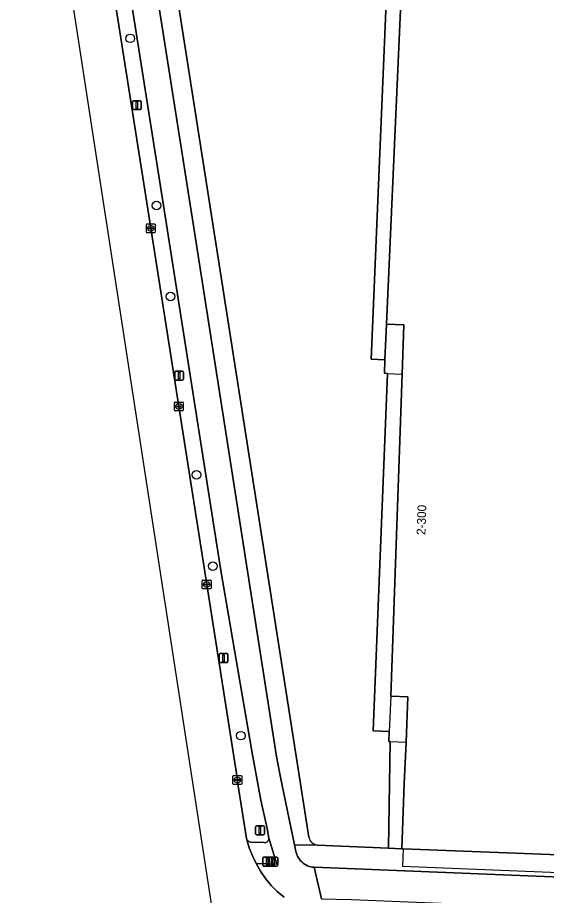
# Model space of a CAD drawing. Extents: x 160888 to 161385, y 386490 to 386908.
# Drawn here: x 160887.8 to 160947.8, y 386737.3 to 386837.1 of the extents above; entities that cross this region are included whole.
import ezdxf

# ---------------------------------------------------------------- set-up
doc = ezdxf.new("R2010")
doc.units = 0
for name, color, linetype in [('IMGEO_Berm_groen', 7, 'Continuous'), ('IMGEO_Boom', 7, 'Continuous'), ('IMGEO_Drukknoppaal', 7, 'Continuous'), ('IMGEO_Erf', 7, 'Continuous'), ('IMGEO_Fietspad_gesloten', 7, 'Continuous'), ('IMGEO_Groenvoorziening', 7, 'Continuous'), ('IMGEO_Kolk', 7, 'Continuous'), ('IMGEO_Lichtmast', 7, 'Continuous'), ('IMGEO_Pand', 7, 'Continuous'), ('IMGEO_Pand_nummerreeks', 7, 'Continuous'), ('IMGEO_Pand_overbouw', 7, 'Continuous'), ('IMGEO_Rijbaan_lokaal_gesloten', 7, 'Continuous'), ('IMGEO_Verkeersbordpaal', 7, 'Continuous'), ('IMGEO_Verkeersregelinstallatiepaal', 7, 'Continuous'), ('IMGEO_Voetpad_gesloten', 7, 'Continuous'), ('IMGEO_Voetpad_open', 7, 'Continuous')]:
    doc.layers.add(name, color=color, linetype=linetype)

msp = doc.modelspace()

# ---------------------------------------------------------------- linework, layer by layer
at = {"layer": 'IMGEO_Berm_groen'}
for points in [[(160895.489, 386860.369), (160895.508, 386860.258), (160895.636, 386859.48), (160895.937, 386857.577), (160898.944, 386838.332), (160902.899, 386813.113), (160906.087, 386792.878), (160909.252, 386772.655), (160912.737, 386750.44), (160912.804, 386750), (160913.758, 386743.775)], [(160904.689, 386813.559), (160897.429, 386859.589), (160897.273, 386860.565)], [(160916.31, 386743.822), (160916.107, 386744.917), (160915.406, 386748.161), (160915.067, 386750), (160914.38, 386753.725), (160910.872, 386774.235), (160904.689, 386813.559)], [(160914.246, 386743.387), (160915.791, 386743.32)]]:
    msp.add_lwpolyline(points, dxfattribs=at)
for centre, radius, start, end in [((160914.327, 386743.989), 0.608, 200.64836, 262.37649), ((160915.811, 386743.819), 0.499, 267.70354, 0.38865)]:
    msp.add_arc(centre, radius, start, end, dxfattribs=at)
at = {"layer": 'IMGEO_Boom'}
for centre in [(160900.576, 386834.696), (160903.554, 386815.703), (160905.132, 386805.364), (160908.087, 386785.118), (160909.949, 386774.72), (160913.128, 386755.473)]:
    msp.add_circle(centre, 0.489, dxfattribs=at)
at = {"layer": 'IMGEO_Drukknoppaal'}
for p, q in [((160916.348, 386740.753), (160916.348, 386741.553)), ((160916.348, 386741.553), (160916.348, 386740.753)), ((160916.448, 386741.653), (160917.238, 386741.653)), ((160917.238, 386741.653), (160916.448, 386741.653)), ((160917.338, 386741.553), (160917.338, 386740.753)), ((160917.338, 386740.753), (160917.338, 386741.553)), ((160917.238, 386740.653), (160916.448, 386740.653)), ((160916.448, 386740.653), (160917.238, 386740.653))]:
    msp.add_line(p, q, dxfattribs=at)
msp.add_lwpolyline([(160916.768, 386741.528), (160916.918, 386741.528), (160916.918, 386740.778), (160916.768, 386740.778), (160916.768, 386741.528)], dxfattribs=at)
for centre, start, end in [((160916.448, 386741.553), 90, 180), ((160916.448, 386741.553), 90, 180), ((160917.238, 386741.553), 0, 90), ((160917.238, 386741.553), 360, 90), ((160916.448, 386740.753), 180, 270), ((160916.448, 386740.753), 180, 270), ((160917.238, 386740.753), 270, 0), ((160917.238, 386740.753), 270, 0)]:
    msp.add_arc(centre, 0.1, start, end, dxfattribs=at)
at = {"layer": 'IMGEO_Erf'}
msp.add_lwpolyline([(160931.458, 386796.556), (160931.656, 386802.139), (160929.668, 386802.21), (160929.5, 386798.18), (160929.436, 386796.639), (160929.806, 386796.624), (160928.176, 386756.029), (160929.987, 386755.938), (160929.938, 386754.813), (160930.114, 386754.806), (160930.028, 386750), (160929.897, 386742.707), (160931.403, 386742.634), (160931.703, 386750), (160931.896, 386754.732), (160932.106, 386759.876), (160930.162, 386759.955)], close=True, dxfattribs=at)
at = {"layer": 'IMGEO_Fietspad_gesloten'}
for points in [[(160922.279, 386736.94), (160921.46, 386740.524), (160921.286, 386740.54), (160921.091, 386740.575), (160920.9, 386740.627), (160920.714, 386740.696), (160920.534, 386740.781), (160920.364, 386740.882), (160920.203, 386740.998), (160920.052, 386741.128), (160919.915, 386741.27), (160919.79, 386741.425), (160919.68, 386741.59), (160919.584, 386741.764), (160919.505, 386741.946), (160919.443, 386742.134), (160919.397, 386742.327), (160919.245, 386743.063), (160917.807, 386750), (160917.572, 386751.136), (160917.197, 386753.124), (160907.589, 386814.399), (160899.722, 386864.375)], [(160897.429, 386859.589), (160904.689, 386813.559), (160910.872, 386774.235), (160914.38, 386753.725), (160915.067, 386750), (160915.406, 386748.161), (160916.107, 386744.917), (160916.31, 386743.822), (160917.205, 386740.862), (160914.891, 386740.934), (160915.378, 386740.062), (160915.94, 386739.237), (160916.574, 386738.465), (160917.275, 386737.753), (160918.036, 386737.106)], [(160992.282, 386737.671), (160955.08, 386739.168), (160921.46, 386740.524), (160922.279, 386736.94), (160925.661, 386736.849), (160955.395, 386735.634), (160990.998, 386734.2), (160994.79, 386734.023), (160998.243, 386734.057), (161000, 386734.178), (161002.436, 386734.648), (161005.984, 386735.898), (161019.969, 386741.623)]]:
    msp.add_lwpolyline(points, dxfattribs=at)
at = {"layer": 'IMGEO_Groenvoorziening'}
for points in [[(160930.929, 386869.413), (160919.86, 386869.902), (160901.002, 386870.642), (160909.808, 386814.589), (160919.923, 386750), (160920.871, 386743.948)], [(160921.858, 386743.044), (160929.897, 386742.707), (160930.028, 386750), (160930.114, 386754.806), (160929.938, 386754.813), (160929.987, 386755.938), (160928.176, 386756.029), (160929.806, 386796.624), (160929.436, 386796.639), (160929.5, 386798.18), (160927.927, 386798.235), (160930.929, 386869.413)]]:
    msp.add_lwpolyline(points, dxfattribs=at)
msp.add_arc((160921.926, 386744.109), 1.067, 188.65599, 266.37045, dxfattribs=at)
at = {"layer": 'IMGEO_Kolk'}
for p, q in [((160902.398, 386812.687), (160902.398, 386813.539)), ((160902.473, 386813.613), (160903.325, 386813.613)), ((160902.657, 386813.107), (160902.657, 386813.119)), ((160903.095, 386813.07), (160902.697, 386813.07)), ((160902.7, 386813.156), (160903.098, 386813.156)), ((160902.909, 386812.833), (160902.884, 386812.833)), ((160902.886, 386813.393), (160902.911, 386813.393)), ((160903.141, 386813.119), (160903.141, 386813.107)), ((160903.399, 386813.539), (160903.399, 386812.687)), ((160903.325, 386812.613), (160902.473, 386812.613)), ((160905.586, 386792.452), (160905.586, 386793.304)), ((160905.661, 386793.378), (160906.513, 386793.378)), ((160905.845, 386792.872), (160905.845, 386792.884)), ((160906.283, 386792.835), (160905.885, 386792.835)), ((160905.888, 386792.921), (160906.286, 386792.921)), ((160906.074, 386793.158), (160906.099, 386793.158)), ((160906.329, 386792.884), (160906.329, 386792.872)), ((160906.587, 386793.304), (160906.587, 386792.452)), ((160906.513, 386792.378), (160905.661, 386792.378)), ((160906.097, 386792.598), (160906.072, 386792.598)), ((160908.751, 386772.229), (160908.751, 386773.081)), ((160908.826, 386773.155), (160909.678, 386773.155)), ((160909.239, 386772.935), (160909.264, 386772.935)), ((160909.752, 386773.081), (160909.752, 386772.229)), ((160909.678, 386772.155), (160908.826, 386772.155)), ((160909.01, 386772.649), (160909.01, 386772.661)), ((160909.448, 386772.612), (160909.05, 386772.612)), ((160909.053, 386772.698), (160909.451, 386772.698)), ((160909.262, 386772.375), (160909.237, 386772.375)), ((160909.494, 386772.661), (160909.494, 386772.649)), ((160912.311, 386750.94), (160913.163, 386750.94)), ((160912.236, 386750.014), (160912.236, 386750.866)), ((160913.163, 386749.94), (160912.311, 386749.94)), ((160912.495, 386750.434), (160912.495, 386750.446)), ((160912.933, 386750.397), (160912.535, 386750.397)), ((160912.538, 386750.483), (160912.936, 386750.483)), ((160912.747, 386750.16), (160912.722, 386750.16)), ((160912.724, 386750.72), (160912.749, 386750.72)), ((160912.979, 386750.446), (160912.979, 386750.434)), ((160913.237, 386750.866), (160913.237, 386750.014))]:
    msp.add_line(p, q, dxfattribs=at)
for points in [[(160902.398, 386812.687), (160902.398, 386813.539)], [(160902.473, 386813.613), (160903.325, 386813.613)], [(160903.399, 386813.539), (160903.399, 386812.687)], [(160903.325, 386812.613), (160902.473, 386812.613)], [(160905.586, 386792.452), (160905.586, 386793.304)], [(160905.661, 386793.378), (160906.513, 386793.378)], [(160906.587, 386793.304), (160906.587, 386792.452)], [(160906.513, 386792.378), (160905.661, 386792.378)], [(160908.751, 386772.229), (160908.751, 386773.081)], [(160908.826, 386773.155), (160909.678, 386773.155)], [(160909.752, 386773.081), (160909.752, 386772.229)], [(160909.678, 386772.155), (160908.826, 386772.155)], [(160912.311, 386750.94), (160913.163, 386750.94)], [(160912.236, 386750.014), (160912.236, 386750.866)], [(160913.163, 386749.94), (160912.311, 386749.94)], [(160913.237, 386750.866), (160913.237, 386750.014)]]:
    msp.add_lwpolyline(points, dxfattribs=at)
for centre, radius, start, end in [((160902.475, 386813.537), 0.0765, 91.55205, 178.44795), ((160902.475, 386813.537), 0.0765, 91.55205, 178.44795), ((160902.697, 386813.116), 0.0403, 85.87752, 175.75265), ((160902.694, 386813.106), 0.0366, 178.93798, 274.71019), ((160903.098, 386813.113), 0.043, 264.86636, 352.45326), ((160903.102, 386813.118), 0.0386, 1.73085, 96.63898), ((160903.323, 386813.537), 0.0765, 1.55205, 88.44795), ((160903.323, 386813.537), 0.0765, 1.55205, 88.44795), ((160902.475, 386812.689), 0.0765, 181.55205, 268.44795), ((160902.475, 386812.689), 0.0765, 181.55205, 268.44795), ((160903.323, 386812.689), 0.0765, 271.55205, 358.44795), ((160903.323, 386812.689), 0.0765, 271.55205, 358.44795), ((160905.663, 386793.302), 0.0765, 91.55205, 178.44795), ((160905.663, 386793.302), 0.0765, 91.55205, 178.44795), ((160905.885, 386792.881), 0.0403, 85.87752, 175.75265), ((160905.882, 386792.871), 0.0366, 178.93798, 274.71019), ((160906.286, 386792.878), 0.043, 264.86636, 352.45326), ((160906.29, 386792.883), 0.0386, 1.73085, 96.63898), ((160906.511, 386793.302), 0.0765, 1.55205, 88.44795), ((160906.511, 386793.302), 0.0765, 1.55205, 88.44795), ((160905.663, 386792.454), 0.0765, 181.55205, 268.44795), ((160905.663, 386792.454), 0.0765, 181.55205, 268.44795), ((160906.511, 386792.454), 0.0765, 271.55205, 358.44795), ((160906.511, 386792.454), 0.0765, 271.55205, 358.44795), ((160908.828, 386773.079), 0.0765, 91.55205, 178.44795), ((160908.828, 386773.079), 0.0765, 91.55205, 178.44795), ((160909.676, 386773.079), 0.0765, 1.55205, 88.44795), ((160909.676, 386773.079), 0.0765, 1.55205, 88.44795), ((160908.828, 386772.231), 0.0765, 181.55205, 268.44795), ((160908.828, 386772.231), 0.0765, 181.55205, 268.44795), ((160909.05, 386772.658), 0.0403, 85.87752, 175.75265), ((160909.047, 386772.648), 0.0366, 178.93798, 274.71019), ((160909.451, 386772.655), 0.043, 264.86636, 352.45326), ((160909.455, 386772.66), 0.0386, 1.73085, 96.63898), ((160909.676, 386772.231), 0.0765, 271.55205, 358.44795), ((160909.676, 386772.231), 0.0765, 271.55205, 358.44795), ((160912.313, 386750.864), 0.0765, 91.55205, 178.44795), ((160912.313, 386750.864), 0.0765, 91.55205, 178.44795), ((160913.161, 386750.864), 0.0765, 1.55205, 88.44795), ((160913.161, 386750.864), 0.0765, 1.55205, 88.44795), ((160912.313, 386750.016), 0.0765, 181.55205, 268.44795), ((160912.313, 386750.016), 0.0765, 181.55205, 268.44795), ((160912.535, 386750.443), 0.0403, 85.87752, 175.75265), ((160912.532, 386750.433), 0.0366, 178.93798, 274.71019), ((160912.936, 386750.44), 0.043, 264.86636, 352.45326), ((160912.94, 386750.445), 0.0386, 1.73085, 96.63898), ((160913.161, 386750.016), 0.0765, 271.55205, 358.44795), ((160913.161, 386750.016), 0.0765, 271.55205, 358.44795)]:
    msp.add_arc(centre, radius, start, end, dxfattribs=at)
for centre, major_axis, ratio, start_param, end_param in [((160902.885, 386813.113), (-0.387, 0.002), 0.722429, 4.712389, 7.853982), ((160902.91, 386813.113), (-0.39, 0.002), 0.717154, 1.570796, 4.712389), ((160906.073, 386792.878), (-0.387, 0.002), 0.722429, 4.712389, 7.853982), ((160906.098, 386792.878), (-0.39, 0.002), 0.717154, 1.570796, 4.712389), ((160909.238, 386772.655), (-0.387, 0.002), 0.722429, 4.712389, 7.853982), ((160909.263, 386772.655), (-0.39, 0.002), 0.717154, 1.570796, 4.712389), ((160912.723, 386750.44), (-0.387, 0.002), 0.722429, 4.712389, 7.853982), ((160912.748, 386750.44), (-0.39, 0.002), 0.717154, 1.570796, 4.712389)]:
    msp.add_ellipse(centre, major_axis=major_axis, ratio=ratio, start_param=start_param, end_param=end_param, dxfattribs=at)
at = {"layer": 'IMGEO_Lichtmast'}
for p, q in [((160900.834, 386826.706), (160900.834, 386827.506)), ((160900.834, 386827.506), (160900.834, 386826.706)), ((160900.934, 386827.606), (160901.724, 386827.606)), ((160901.724, 386827.606), (160900.934, 386827.606)), ((160901.824, 386827.506), (160901.824, 386826.706)), ((160901.824, 386826.706), (160901.824, 386827.506)), ((160901.724, 386826.606), (160900.934, 386826.606)), ((160900.934, 386826.606), (160901.724, 386826.606)), ((160905.721, 386796.877), (160906.511, 386796.877)), ((160906.511, 386796.877), (160905.721, 386796.877)), ((160905.621, 386795.977), (160905.621, 386796.777)), ((160905.621, 386796.777), (160905.621, 386795.977)), ((160906.511, 386795.877), (160905.721, 386795.877)), ((160905.721, 386795.877), (160906.511, 386795.877)), ((160906.611, 386796.777), (160906.611, 386795.977)), ((160906.611, 386795.977), (160906.611, 386796.777)), ((160910.676, 386763.891), (160910.676, 386764.691)), ((160910.676, 386764.691), (160910.676, 386763.891)), ((160910.776, 386764.791), (160911.566, 386764.791)), ((160911.566, 386764.791), (160910.776, 386764.791)), ((160911.666, 386764.691), (160911.666, 386763.891)), ((160911.666, 386763.891), (160911.666, 386764.691)), ((160911.566, 386763.791), (160910.776, 386763.791)), ((160910.776, 386763.791), (160911.566, 386763.791))]:
    msp.add_line(p, q, dxfattribs=at)
for points in [[(160901.254, 386827.481), (160901.404, 386827.481), (160901.404, 386826.731), (160901.254, 386826.731), (160901.254, 386827.481)], [(160906.041, 386796.752), (160906.191, 386796.752), (160906.191, 386796.002), (160906.041, 386796.002), (160906.041, 386796.752)], [(160911.096, 386764.666), (160911.246, 386764.666), (160911.246, 386763.916), (160911.096, 386763.916), (160911.096, 386764.666)]]:
    msp.add_lwpolyline(points, dxfattribs=at)
for centre, start, end in [((160900.934, 386827.506), 90, 180), ((160900.934, 386827.506), 90, 180), ((160901.724, 386827.506), 0, 90), ((160901.724, 386827.506), 360, 90), ((160900.934, 386826.706), 180, 270), ((160900.934, 386826.706), 180, 270), ((160901.724, 386826.706), 270, 0), ((160901.724, 386826.706), 270, 0), ((160905.721, 386796.777), 90, 180), ((160905.721, 386796.777), 90, 180), ((160906.511, 386796.777), 0, 90), ((160906.511, 386796.777), 360, 90), ((160905.721, 386795.977), 180, 270), ((160905.721, 386795.977), 180, 270), ((160906.511, 386795.977), 270, 0), ((160906.511, 386795.977), 270, 0), ((160910.776, 386764.691), 90, 180), ((160910.776, 386764.691), 90, 180), ((160911.566, 386764.691), 0, 90), ((160911.566, 386764.691), 360, 90), ((160910.776, 386763.891), 180, 270), ((160910.776, 386763.891), 180, 270), ((160911.566, 386763.891), 270, 0), ((160911.566, 386763.891), 270, 0)]:
    msp.add_arc(centre, 0.1, start, end, dxfattribs=at)
at = {"layer": 'IMGEO_Pand'}
msp.add_lwpolyline([(160932.347, 386861.777), (160929.668, 386802.21), (160931.656, 386802.139), (160931.458, 386796.556), (160930.162, 386759.955), (160932.106, 386759.876), (160931.896, 386754.732), (160931.703, 386750), (160931.403, 386742.634), (160931.578, 386742.627), (160951.188, 386741.843), (160951.385, 386741.835), (160951.772, 386750), (160952.32, 386763.778), (160952.108, 386763.787), (160950.315, 386763.859), (160951.446, 386797.676), (160949.448, 386797.758), (160951.78, 386847.873)], dxfattribs=at)
at = {"layer": 'IMGEO_Pand_overbouw'}
for points in [[(160929.668, 386802.21), (160929.5, 386798.18), (160929.436, 386796.639), (160929.806, 386796.624), (160931.458, 386796.556), (160931.656, 386802.139)], [(160931.896, 386754.732), (160932.106, 386759.876), (160930.162, 386759.955), (160929.987, 386755.938), (160929.938, 386754.813), (160930.114, 386754.806)], [(160931.578, 386742.627), (160931.495, 386740.644), (160951.101, 386739.86), (160951.188, 386741.843)]]:
    msp.add_lwpolyline(points, close=True, dxfattribs=at)
at = {"layer": 'IMGEO_Rijbaan_lokaal_gesloten'}
for points in [[(160887.77, 386879.356), (160914.501, 386705.629)], [(160918.036, 386737.106), (160917.275, 386737.753), (160916.574, 386738.465), (160915.94, 386739.237), (160915.378, 386740.062), (160914.891, 386740.934), (160914.487, 386741.731), (160914.076, 386742.739), (160913.758, 386743.775), (160912.804, 386750), (160912.737, 386750.44), (160909.252, 386772.655), (160906.087, 386792.878), (160902.899, 386813.113), (160898.944, 386838.332), (160895.937, 386857.577), (160895.636, 386859.48), (160895.508, 386860.258), (160895.489, 386860.369), (160894.934, 386863.689), (160894.371, 386867.052), (160894.361, 386867.114), (160891.251, 386879.23), (160887.77, 386879.356)]]:
    msp.add_lwpolyline(points, dxfattribs=at)
at = {"layer": 'IMGEO_Verkeersbordpaal'}
for p, q in [((160914.813, 386744.323), (160914.813, 386745.123)), ((160914.813, 386745.123), (160914.813, 386744.323)), ((160914.913, 386745.223), (160915.703, 386745.223)), ((160915.703, 386745.223), (160914.913, 386745.223)), ((160915.803, 386745.123), (160915.803, 386744.323)), ((160915.803, 386744.323), (160915.803, 386745.123)), ((160915.703, 386744.223), (160914.913, 386744.223)), ((160914.913, 386744.223), (160915.703, 386744.223))]:
    msp.add_line(p, q, dxfattribs=at)
msp.add_lwpolyline([(160915.233, 386745.098), (160915.383, 386745.098), (160915.383, 386744.348), (160915.233, 386744.348), (160915.233, 386745.098)], dxfattribs=at)
for centre, start, end in [((160914.913, 386745.123), 90, 180), ((160914.913, 386745.123), 90, 180), ((160915.703, 386745.123), 0, 90), ((160915.703, 386745.123), 360, 90), ((160914.913, 386744.323), 180, 270), ((160914.913, 386744.323), 180, 270), ((160915.703, 386744.323), 270, 0), ((160915.703, 386744.323), 270, 0)]:
    msp.add_arc(centre, 0.1, start, end, dxfattribs=at)
at = {"layer": 'IMGEO_Verkeersregelinstallatiepaal'}
for p, q in [((160915.614, 386740.751), (160915.614, 386741.551)), ((160915.614, 386741.551), (160915.614, 386740.751)), ((160915.714, 386741.651), (160916.504, 386741.651)), ((160916.504, 386741.651), (160915.714, 386741.651)), ((160916.604, 386741.551), (160916.604, 386740.751)), ((160916.604, 386740.751), (160916.604, 386741.551)), ((160916.504, 386740.651), (160915.714, 386740.651)), ((160915.714, 386740.651), (160916.504, 386740.651))]:
    msp.add_line(p, q, dxfattribs=at)
msp.add_lwpolyline([(160916.034, 386741.526), (160916.184, 386741.526), (160916.184, 386740.776), (160916.034, 386740.776), (160916.034, 386741.526)], dxfattribs=at)
for centre, start, end in [((160915.714, 386741.551), 90, 180), ((160915.714, 386741.551), 90, 180), ((160916.504, 386741.551), 0, 90), ((160916.504, 386741.551), 360, 90), ((160915.714, 386740.751), 180, 270), ((160915.714, 386740.751), 180, 270), ((160916.504, 386740.751), 270, 0), ((160916.504, 386740.751), 270, 0)]:
    msp.add_arc(centre, 0.1, start, end, dxfattribs=at)
at = {"layer": 'IMGEO_Voetpad_gesloten'}
msp.add_lwpolyline([(160951.188, 386741.843), (160931.578, 386742.627), (160931.403, 386742.634), (160929.897, 386742.707), (160921.858, 386743.044), (160919.245, 386743.063), (160919.397, 386742.327), (160919.443, 386742.134), (160919.505, 386741.946), (160919.584, 386741.764), (160919.68, 386741.59), (160919.79, 386741.425), (160919.915, 386741.27), (160920.052, 386741.128), (160920.203, 386740.998), (160920.364, 386740.882), (160920.534, 386740.781), (160920.714, 386740.696), (160920.9, 386740.627), (160921.091, 386740.575), (160921.286, 386740.54), (160921.46, 386740.524), (160955.08, 386739.168)], dxfattribs=at)
at = {"layer": 'IMGEO_Voetpad_open'}
for points in [[(160909.808, 386814.589), (160901.002, 386870.642), (160901.306, 386873.07), (160901.489, 386877.014)], [(160898.426, 386872.614), (160898.823, 386870.088), (160899.722, 386864.375), (160907.589, 386814.399), (160917.197, 386753.124), (160917.572, 386751.136), (160917.807, 386750), (160919.245, 386743.063), (160921.858, 386743.044)], [(160930.929, 386869.413), (160927.927, 386798.235), (160929.5, 386798.18), (160929.668, 386802.21), (160932.347, 386861.777)], [(160920.871, 386743.948), (160919.923, 386750), (160909.808, 386814.589)], [(160913.758, 386743.775), (160914.076, 386742.739), (160914.487, 386741.731), (160914.891, 386740.934), (160917.205, 386740.862), (160916.31, 386743.822)], [(160915.791, 386743.32), (160914.246, 386743.387)]]:
    msp.add_lwpolyline(points, dxfattribs=at)
for centre, radius, start, end in [((160921.926, 386744.109), 1.067, 188.65599, 266.37045), ((160914.327, 386743.989), 0.608, 200.64836, 262.37649), ((160915.811, 386743.819), 0.499, 267.70354, 0.38865)]:
    msp.add_arc(centre, radius, start, end, dxfattribs=at)

# ---------------------------------------------------------------- texts
at = {"layer": 'IMGEO_Pand_nummerreeks'}
msp.add_text('2-300', height=1, rotation=87.97164, dxfattribs=at).set_placement((160934.092, 386778.259))

doc.saveas('drawing.dxf')
